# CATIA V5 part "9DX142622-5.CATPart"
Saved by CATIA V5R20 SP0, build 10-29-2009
Part number: 9DX142622-5
Revision: ANY
Definition: UNKNOWN
Nomenclature: 9DX142622-5
Source: Unknown
Bounding box of the stored display mesh (mm): x -10.5 to 10.5, y 0 to 109, z -10.5 to 10.5
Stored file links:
  C:\Users\Utente\Desktop\IO LAVORO\3D X SITO CF\CUMSA\3D files DX\DX 142622\9DX142622-5.CATPart
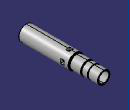
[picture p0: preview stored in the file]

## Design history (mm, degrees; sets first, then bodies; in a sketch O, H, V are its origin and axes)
Body1 "Chaflán2" (main body)
  Solid1: solid without history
